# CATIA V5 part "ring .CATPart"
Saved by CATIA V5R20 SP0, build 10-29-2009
Part number: ring
Material "DS star": density 1000 kg/m3
Material "Light Beige": density 7860 kg/m3, Young's modulus 2e+11 Pa, Poisson ratio 0.266
Material "Multicoloured Flag"
Bounding box of the stored display mesh (mm): x -32.5 to 24.182, y -27.248 to 27.251, z -9.06 to 9.067
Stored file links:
  C:\Users\Machenike\Desktop\ring.CATPart
  D:\CATIAR20\win_b64\startup\materials\Catalog.CATMaterial
  D:\CATIAR20\win_b64\startup\materials\DS_star.jpg
  D:\CATIAR20\win_b64\startup\materials\summer_sky.jpg
  D:\CATIAR20\win_b64\startup\materials\sunset.jpg
  D:\CATIAR20\win_b64\startup\materials\yellow_env_512x512.jpg
  D:\CATIAR20\win_b64\startup\materials\wire.png
  D:\CATIAR20\win_b64\startup\materials\floor.jpg
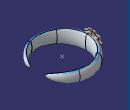
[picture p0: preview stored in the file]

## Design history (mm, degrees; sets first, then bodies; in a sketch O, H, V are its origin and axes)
Set1 "曲面（戒指）", material "Multicoloured Flag"
  Point1: (0, 0, 0)
  Circle1: type CtrRad, Start 15, End 345, Center Point1, Support xy-plane, Radius 25, FirstDirection (1, 0, 0)
  Circle2: type CtrRad, Start 25, End -25, Center Point1, Support zx-plane, Radius 25, FirstDirection (-1, 0, 0)
  Intersect1: ToIntersect1 Circle1, ToIntersect2 Circle2
  Plane1: type OffsetPt, RefPlane yz-plane, RefPoint Intersect1
  Line1: type PtDir, RefPoint Intersect1, Direction (0, 1, 0), Start -70.995, End 70.995
  Point2: type OnPlane, Support Plane1, H 0, V 7, Direction (0, 1, 0)
  Point3: type OnPlane, Support Plane1, H 23.665, V 6, Direction (0, 1, 0)
  Symmetry1: ToTransfor Point3, Reference zx-plane
  Circle3: type 3Points, Start 25, End -25, Element1 Point3, Element2 Point2, Element3 Symmetry1
  Point4: type OnPlane, Support Plane1, H 70.995, V 4, Direction (0, 1, 0)
  Point5: type OnPlane, Support Plane1, H 47.33, V 5, Direction (0, 1, 0)
  Line2: type PtPt, FirstPoint Point5, SecondPoint Point4
  Symmetry2: ToTransfor Line2, Reference Line1
  Conic1: Support Plane1, StartCst Point5, EndCst vertex of Symmetry2, Element1 vertex of Line1, ConicParm 0
  Connect1: Curve1 Conic1, Point1 Point5, Tension1 1, Curve2 Circle3, Point2 Point3, Tension2 1.7
  Split1: ToCut Circle3, Cutting zx-plane
  Split2: ToCut Conic1, Cutting Line1
  Join1: Elements (Split2; Connect1; Split1)
  Symmetry3: ToTransfor Join1, Reference zx-plane
  Join2: Elements (Join1; Symmetry3)
  Sweep1: type Unspec, Profile Circle2, Guide Circle1
  Develop1
  Symmetry4: ToTransfor Develop1, Reference xy-plane
  Join3: Elements (Develop1; Symmetry4)
  Project1: ToProject Join3, Support zx-plane
  Intersect2: ToIntersect1 Project1, ToIntersect2 Join3
  Connect2: Curve1 Project1, Point1 vertex of Intersect2, Tension1 1.1, Point2 vertex of Intersect2, Tension2 1.1
  Connect3: Curve1 Project1, Point1 vertex of Intersect2, Tension1 0.5, Point2 vertex of Intersect2, Tension2 0.5
  Join4: Elements (Connect2; Connect3)
  Split3: ToCut Join3, Cutting Circle1
  Symmetry5: ToTransfor Split3, Reference xy-plane
  Join5: Elements Split3
  Symmetry6: ToTransfor Symmetry5, Reference xy-plane
  Sweep2: type Unspec, Profile Join4, Guide (Symmetry5; Symmetry6), Spine Circle1
Set2 "曲面（花瓣）"
  Circle4: type CtrRad, Start 0, End 180, Center Point1, Support yz-plane, Radius 4, FirstDirection (0, 1, 0)
  CurvePar1: Offset Circle4, Support yz-plane, Offset2 0
  Symmetry7: ToTransfor CurvePar1, Reference xy-plane
  Join6: Elements (Symmetry7; CurvePar1)
  Project2: ToProject Join6, Support Sweep2, Direction (1, 0, 0)
  Extract1: ExtractElem edge of Project2
  Extract2: ExtractElem vertex [face of Project2 | face of Project2]
  Sketch1 on zx-plane, origin (0, 0, 0), H (-1, 0, 0), V (0, 0, 1)
    arc A1 centre (26.9692, -7.1912) radius 3.2043 from (27.2619, -4.0003) to (30.0322, -6.2502) cw
    point P2 (27.2619, -4.0003)
    point P3 (30.0322, -6.2502)
    reference projected point E1 (27.2619, -4.0003) from Extract2
    arc A2 centre (23.3829, -8.8432) radius 6.2049 from (27.2619, -4.0003) to (28.8589, -5.9252) cw
    point P5 (28.8589, -5.9252)
    spline S1 through (28.8589, -5.9252) (28.9513, -6.2928) (29.4875, -7.4914) (29.9501, -6.9131) (30.0322, -6.2502)
    point P6 (28.8589, -5.9252)
    point P9 (30.0322, -6.2502)
    coincidence: P2 E1, P6 P5, P9 P3
  Symmetry8: ToTransfor Circle4, Reference xy-plane
  Join7: Elements (Circle4; Symmetry8)
  Sweep3: type Unspec, Profile Sketch1, Guide Extract1, Spine Join7
  MultiSel1
  Line3: type PtDir, RefPoint Point1, Direction (1, 0, 0), Start 0, End 70.995
  Intersect3: ToIntersect1 Line3, ToIntersect2 Sweep2
  Extract3: ExtractElem vertex of Intersect3
  Near1: MultiElement {translate ToTransfor CircPattern3, Direction (1, 0, 0), Length -30}, ReferenceElement vertex [face of MultiSel1]
Set3 "钻石"
  Plane2: type Offset, RefPlane yz-plane, Offset 2.5, reversed
  Plane3: type Offset, RefPlane yz-plane, Offset 1.5, reversed
  Sketch2 on yz-plane, origin (0, 0, 0), H (0, 1, 0), V (0, 0, 1)
    circle A1 centre (0, 0) radius 5
    radius A1 = 5
  Sketch3 on Plane3, origin (-1.5, 0, 0), H (0, 1, 0), V (0, 0, 1)
    circle A1 centre (-0.1529, 0) radius 4
    point P1 (-0.1529, 0)
    radius A1 = 4
    coincidence: P1 H
  Sketch4 on Plane2, origin (-2.5, 0, 0), H (0, 1, 0), V (0, 0, 1)
    circle A1 centre (0, 0) radius 2
    radius A1 = 2
  Point6: (4, 0, 0)
  Extremum1: Reference Sketch2, Direction (0, 0, 1), Direction2 (0, 0, 1), Direction3 (0, 0, 1)
  Extremum2: Reference Sketch3, Direction (0, 0, 1), Direction2 (0, 0, 1), Direction3 (0, 0, 1)
  Extremum3: Reference Sketch4, Direction (0, 0, 1), Direction2 (0, 0, 1), Direction3 (0, 0, 1)
  Rotate1: ToTransfor Extremum2, Axis X axis, Angle 22.5
  CircPattern1: of Extremum1, instances 8, angular step 45 {= 360.0*1 deg/CircPattern1.AngularNumber}, axis from X axis
  CircPattern2: of Rotate1, instances 8, angular step 45, axis from X axis
  CircPattern3: of Extremum3, instances 8, angular step 45, axis from X axis
  Line4: type PtPt, FirstPoint vertex of CircPattern1, SecondPoint Point6
  LineCorner1: Elements (Extremum1; vertex of CircPattern1; vertex of CircPattern1; vertex of CircPattern1; vertex of CircPattern1; vertex of CircPattern1; vertex of CircPattern1; vertex of CircPattern1)
  LineCorner2: Elements (vertex of CircPattern3; vertex of CircPattern3; vertex of CircPattern3; vertex of CircPattern3; vertex of CircPattern3; vertex of CircPattern3; vertex of CircPattern3; Extremum3)
  Sweep4: type Unspec, Profile Line4, Guide LineCorner1
  Line5: type PtPt, FirstPoint vertex of CircPattern3, SecondPoint vertex of CircPattern2
  Line6: type PtPt, FirstPoint vertex of CircPattern2, SecondPoint vertex of CircPattern3
  Line7: type PtPt, FirstPoint vertex of CircPattern2, SecondPoint vertex of CircPattern1
  Line8: type PtPt, FirstPoint vertex of CircPattern2, SecondPoint vertex of CircPattern1
  Line9: type PtPt, FirstPoint vertex of CircPattern3, SecondPoint vertex of CircPattern2
  Line10: type PtPt, FirstPoint vertex of CircPattern2, SecondPoint vertex of CircPattern2
  Fill1: Boundary (Line9; Line5; Line10)
  DatumCurve1 to DatumCurve8
  Fill2: Boundary (Line7; DatumCurve3; Line8)
  DatumCurve9 to DatumCurve16
  Fill3: Boundary (DatumCurve13; Line6; Line5)
  CircPattern4: of Fill3, instances 8, angular step 45 {= 360.0*1 deg/CircPattern4.AngularNumber}, axis from X axis
  CircPattern5: of Fill1, instances 8, angular step 45, axis from X axis
  CircPattern6: of Fill2, instances 8, angular step 45, axis from X axis
  Fill4: Boundary (Line10; edge of CircPattern6; Line7)
  CircPattern7: of Fill4, instances 8, angular step 45, axis from X axis
  Fill5: Boundary (DatumCurve16; DatumCurve9; DatumCurve10; DatumCurve11; DatumCurve12; DatumCurve13; DatumCurve14; DatumCurve15)
Body1 "指环" (main body)
Body2 "宝石", material "DS star"
  Join8: Elements ({translate ToTransfor Sweep4, Direction (1, 0, 0), Length -30}; {translate ToTransfor CircPattern6, Direction (1, 0, 0), Length -30}; {translate ToTransfor CircPattern7, Direction (1, 0, 0), Length -30}; {translate ToTransfor Fill4, Direction (1, 0, 0), Length -30}; {translate ToTransfor Fill1, Direction (1, 0, 0), Length -30}; {translate ToTransfor Fill3, Direction (1, 0, 0), Length -30}; {translate ToTransfor CircPattern5, Direction (1, 0, 0), Length -30}; {translate ToTransfor Fill5, Direction (1, 0, 0), Length -30}; {translate ToTransfor CircPattern4, Direction (1, 0, 0), Length -30}; {translate ToTransfor Fill2, Direction (1, 0, 0), Length -30})
  CloseSurface1: CloseElement Join8
Body3 "花瓣", material "Light Beige"
  CloseSurface2: CloseElement Sweep3
Body4 "戒指"
  CloseSurface3: CloseElement Sweep2
Relations
  Point3.H = （`测量边线.1\长度` /2-1mm）/3 (deactivated)
  Point3.H = `戒指曲面\直线.1` -1mm (deactivated)
  MultiSel1.Length = MultiSel1.Length +20mm (deactivated)
  MultiSel1.Length = -MultiSel1.Length -2.2mm (deactivated)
